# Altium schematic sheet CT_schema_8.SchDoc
size 254 x 194 mm
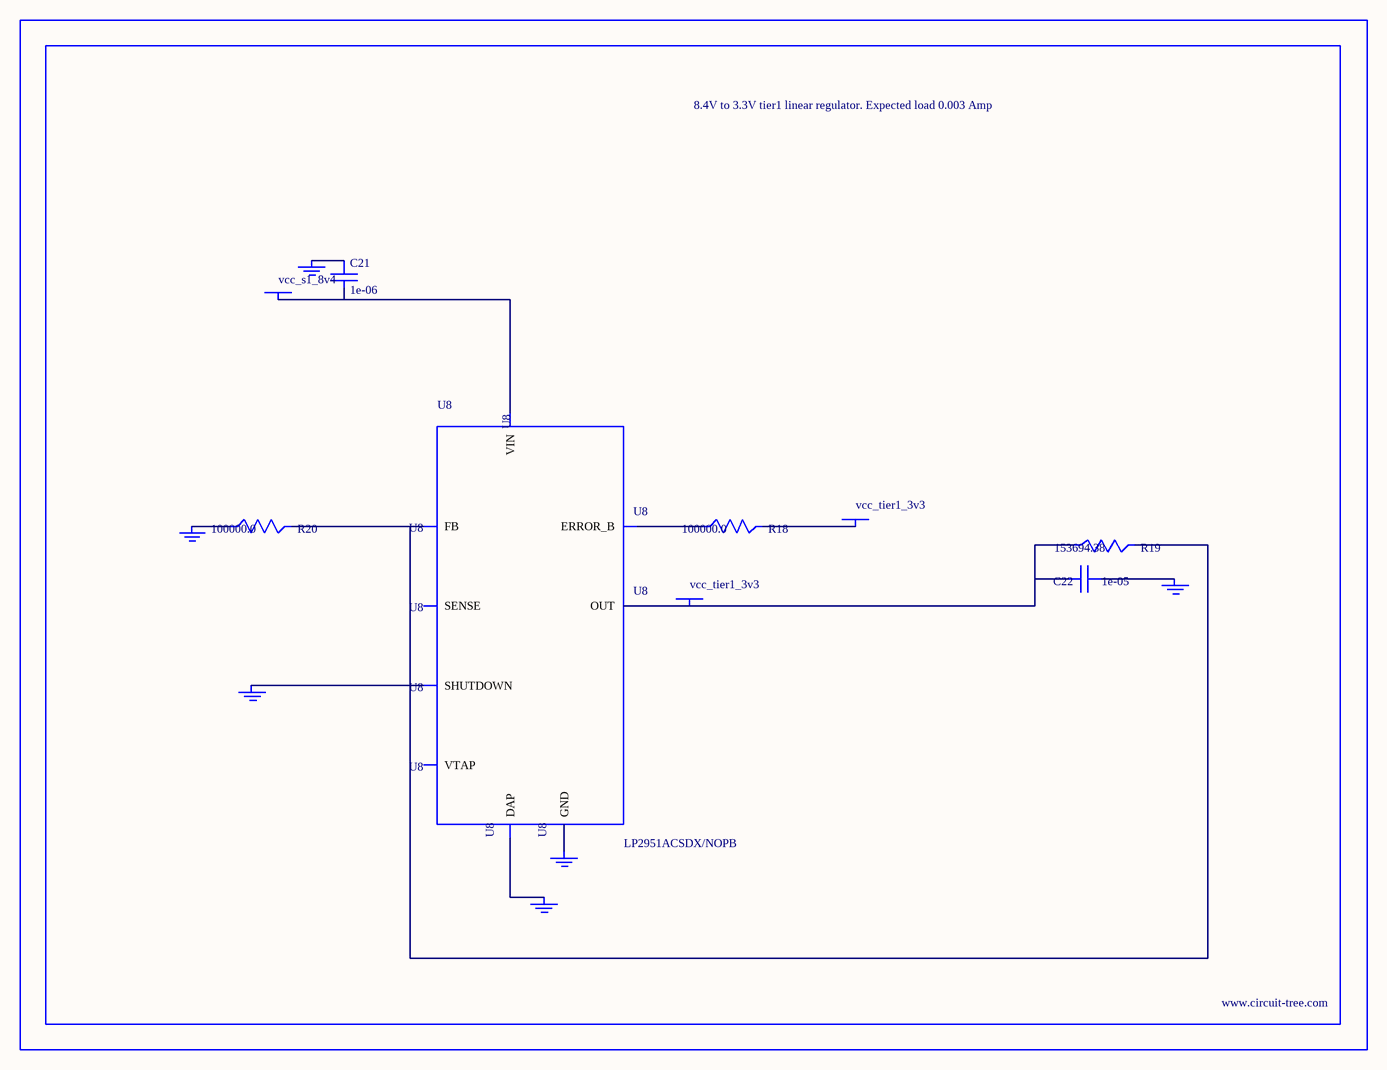
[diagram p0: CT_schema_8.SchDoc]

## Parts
BORDER7  (no value)
C21  1e-06  [C0603]
C22  1e-05  [C1210]
GND_INSTANCE_7_0  (no value)
GND_INSTANCE_7_1  (no value)
GND_INSTANCE_7_2  (no value)
GND_INSTANCE_7_3  (no value)
GND_INSTANCE_7_4  (no value)
GND_INSTANCE_7_5  (no value)
POWER_INSTANCE_7_0  vcc_tier1_3v3
POWER_INSTANCE_7_1  vcc_s1_8v4
POWER_INSTANCE_7_2  vcc_tier1_3v3
R18  100000.0  [R0603]
R19  153694.38  [R0603]
R20  100000.0  [R0603]
U8  LP2951ACSDX/NOPB  [WSON-8]

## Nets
NetC21_1: C21.1 GND_INSTANCE_7_3.0(GND)
NetC21_2: C21.2 POWER_INSTANCE_7_1.0(PWR) U8.8(VIN)
NetC22_1: C22.1 GND_INSTANCE_7_0.0(GND)
NetC22_2: C22.2 POWER_INSTANCE_7_2.0(PWR) R19.1 U8.1(OUT)
NetGND_INSTANCE_7_1_0: GND_INSTANCE_7_1.0(GND) U8.3(SHUTDOWN)
NetGND_INSTANCE_7_2_0: GND_INSTANCE_7_2.0(GND) R20.1
NetGND_INSTANCE_7_4_0: GND_INSTANCE_7_4.0(GND) U8.PAD(DAP)
NetGND_INSTANCE_7_5_0: GND_INSTANCE_7_5.0(GND) U8.4(GND)
NetPOWER_INSTANCE_7_0_0: POWER_INSTANCE_7_0.0(PWR) R18.2
NetR18_1: R18.1 U8.5(ERROR_B)
NetR19_2: R19.2 R20.2 U8.7(FB)

Not connected (* = marked no-connect by the designer): U8 2(SENSE) 6(VTAP)

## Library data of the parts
BORDER7 = BORDER_PAGE7
C21 = C0603C105K3RACTU
C22 = GRM32DR61E106MA12L
GND_INSTANCE_7_0-GND_INSTANCE_7_5 = GND
POWER_INSTANCE_7_0-POWER_INSTANCE_7_2 = PWR
R18 R20 = RC0603JR-07100KL
R19 = R19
